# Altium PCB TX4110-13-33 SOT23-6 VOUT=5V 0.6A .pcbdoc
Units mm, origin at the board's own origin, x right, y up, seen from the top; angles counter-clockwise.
Board outline 37.13 x 43.21 mm, 2 copper layers (Top Layer, Bottom Layer); 14 components, 13 nets, 38 pads, 95 vias.
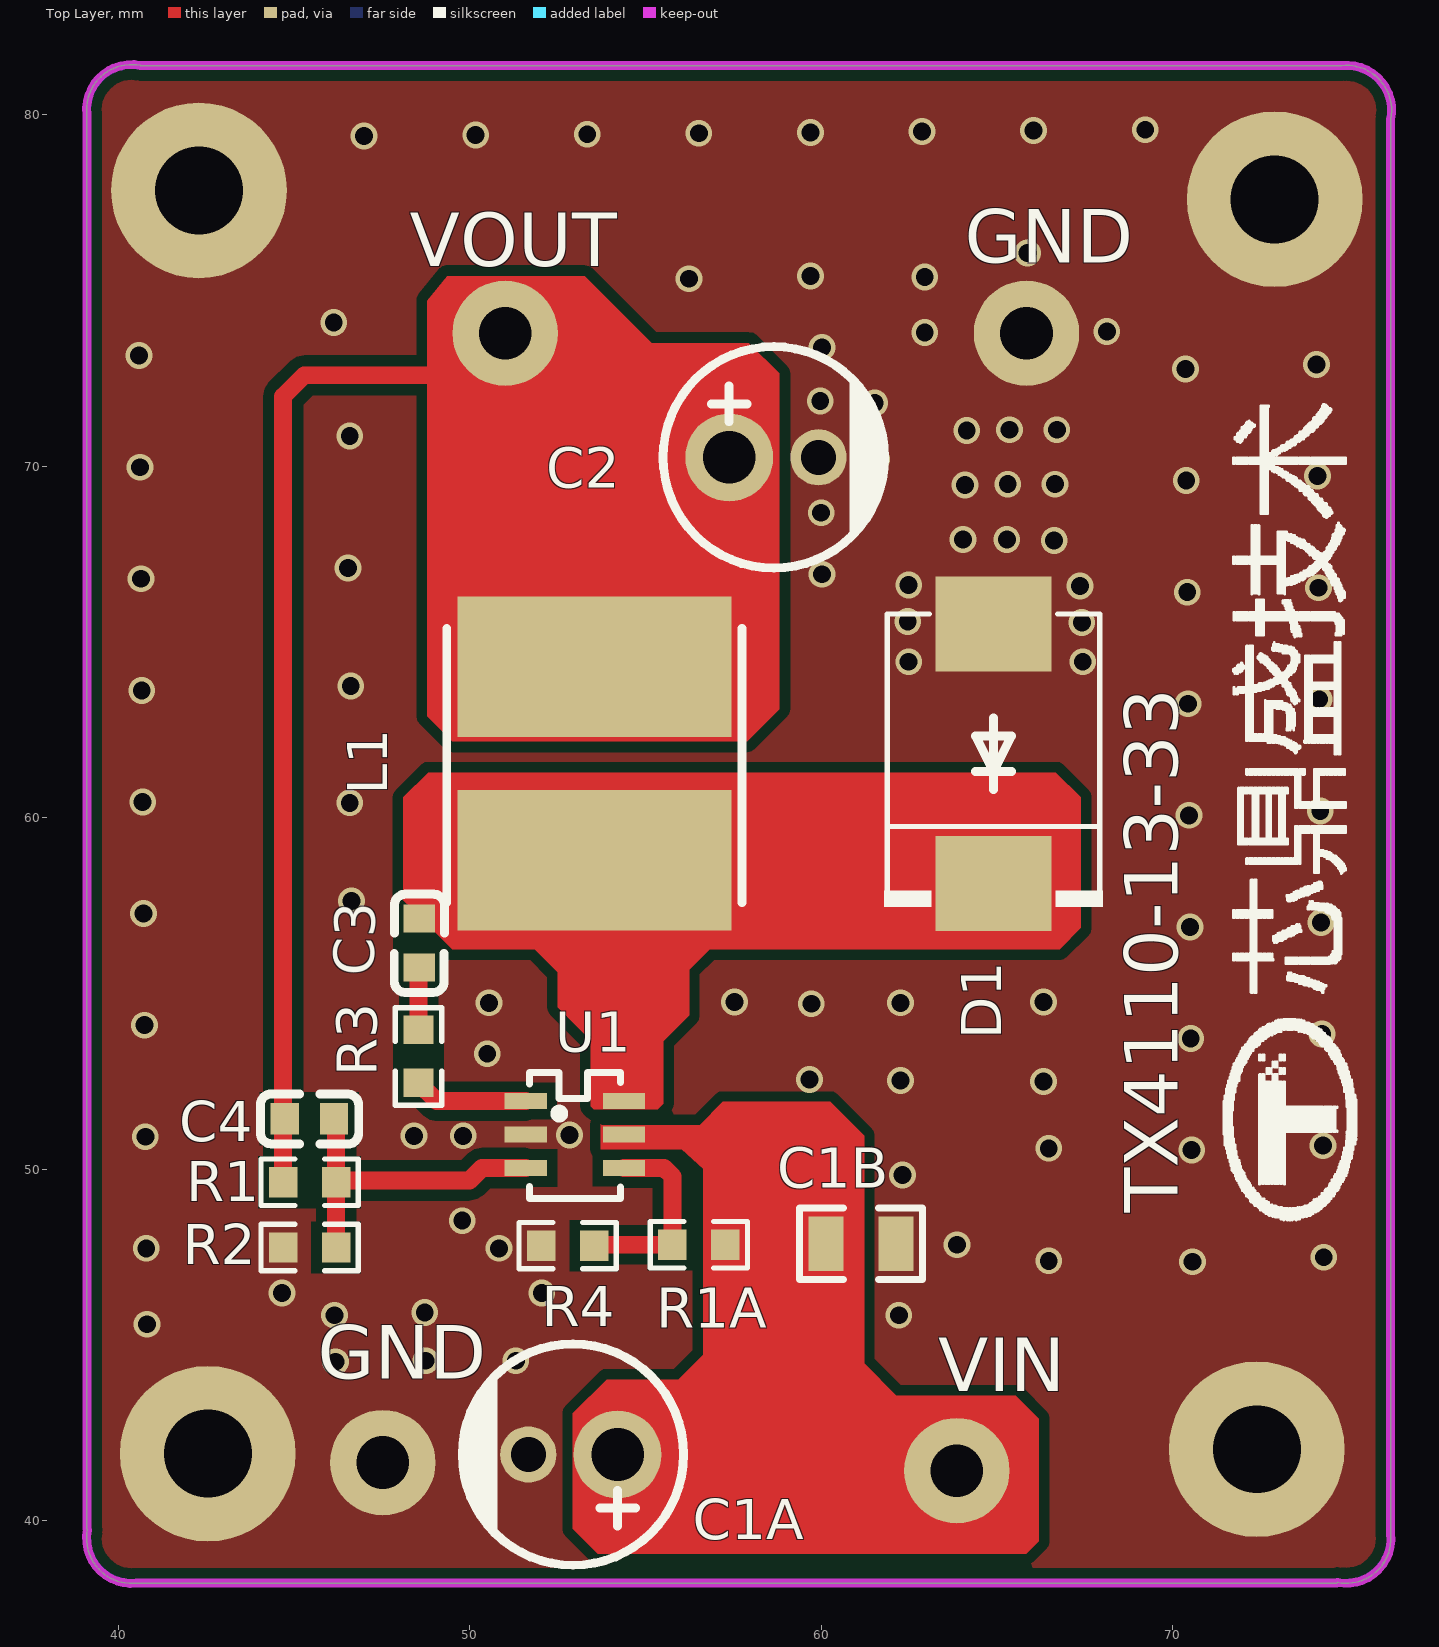
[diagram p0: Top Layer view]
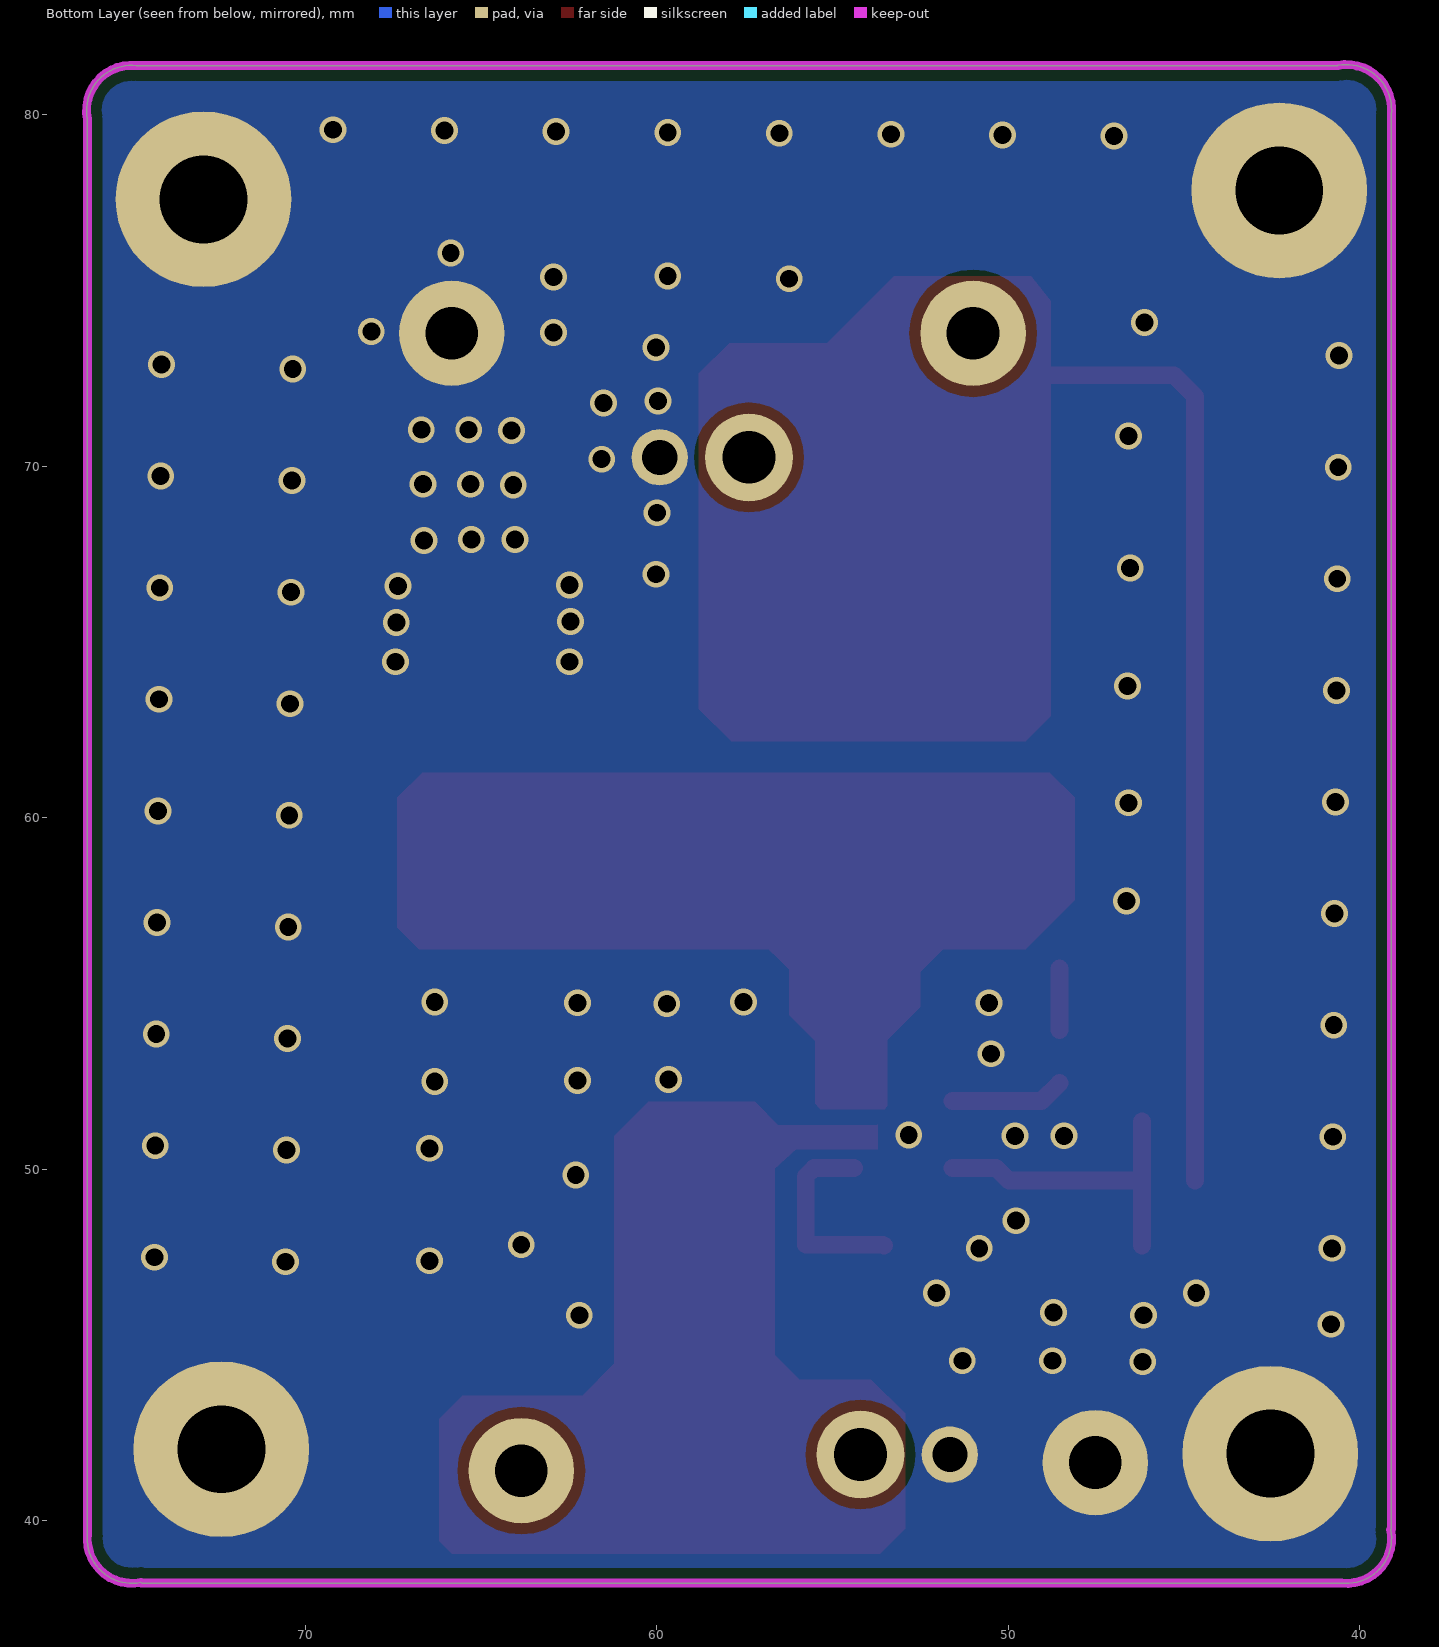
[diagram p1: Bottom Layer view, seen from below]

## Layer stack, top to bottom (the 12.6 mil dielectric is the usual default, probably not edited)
Top Layer: signal copper 0.0356
Dielectric: dielectric 0.32, FR-4, Dk 4.8
Bottom Layer: signal copper 0.0356

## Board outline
40.513,38.227 cw(c40.372,39.496) 39.121,39.746 39.104,39.763 39.104,80.015 cw(c40.372,80.155) 40.622,81.407 40.628,81.402 74.808,81.402 cw(c74.948,80.133) 76.2,79.883 76.199,79.882 76.199,39.638 cw(c74.93,39.497) 74.68,38.245 74.661,38.227

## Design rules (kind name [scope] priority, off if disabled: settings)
Clearance [All] p1: gap=0.305
PlaneConnect [All] p1: planeconnectstyle=Direct reliefexpansion=0.508 reliefentries=4 reliefconductorwidth=0.254 reliefairgap=0.254
PolygonConnect [All] p1: connectstyle=Direct reliefconductorwidth=0.254 reliefentries=4 polygonreliefangle="90 Angle"
RoutingVias [All] p1: holewidth=0.711 width=1.27 viastyle="Through Hole" minholewidth=0.711 minwidth=1.27 maxholewidth=0.711 maxwidth=1.27
SilkscreenOverComponentPads [All] p1: minsilkscreentomaskgap=0.254
SolderMaskExpansion [All] p1: expansion=0.102
TestPointUsage [All] p1: valid=0 allowmultiple=FALSE
Testpoint [All] p1: side=3 testpointundercomponent=TRUE minsize=1.016 maxsize=2.54 preferedsize=1.524 minholesize=0 maxholesize=1.016 preferedholesize=0.813 testpointgrid=0.025 style=297 order=0-112345678
Width [All] p1: maxlimit=2.54 minlimit=0.508 preferedwidth=0.508
22 further rules are at their usual default settings.

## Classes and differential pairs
net class NewClass: VIN

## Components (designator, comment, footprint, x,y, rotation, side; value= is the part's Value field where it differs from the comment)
C1A "100UF" CAP-TH_BD6.3-P2.50-D1.0-FD 52.934,41.885 r180 top (schematic designator C1)
C1B "0.1u" 0805 62.128,47.879 r180 top (schematic designator C6)
C2 "470uF" CAP-TH_BD6.3-P2.50-D1.0-FD 58.649,70.256 r0 top
C3 "0.1u" C0603 48.565,56.439 r90 top (schematic designator C4)
C4 "NC" C0603 45.433,51.435 r180 top (schematic designator C6)
D1 "SS510SMC" SMC_L6.9-W5.9-LS7.9-RD 64.897,61.824 r90 top (schematic designator D2)
L1 "10uH" IND-SMD_L7.8-W7.0_GCD75 53.543,61.544 r90 top (schematic designator L2)
R1 "300K 1%" R0603 45.441,49.632 r180 top (schematic designator R4)
R1A "1k" R0603 56.515,47.854 r180 top (schematic designator R3)
R2 "51k 1%" R0603 45.441,47.777 r0 top (schematic designator R5)
R3 "5.1k" R0603 48.539,53.213 r270 top (schematic designator R2)
R4 "NC" R0603 52.781,47.828 r0 top (schematic designator R3)
TX4110-13-33 "Comment" LOGO 72.822,51.435 r90 top
U1 "TX4137" SOT-23-6 51.587,51.943 r0 top

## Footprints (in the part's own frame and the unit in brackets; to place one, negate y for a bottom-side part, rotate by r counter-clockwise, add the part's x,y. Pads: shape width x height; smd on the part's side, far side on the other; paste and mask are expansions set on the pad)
0805 [mm]
  rect 1x1.55 smd: 1(0,0) 2(2,0)
  silkscreen extent -0.75,-1.02 2.75,1.02
C0603 [mm]
  rect 0.8x0.9 smd: 1(-0.7,0) 2(0.7,0)
  silkscreen extent -1.41,-0.71 1.39,0.72
CAP-TH_BD6.3-P2.50-D1.0-FD [mm]
  round 2.5 hole 1.5: 1(-1.27,0)
  round 1.6 hole 1: 2(1.27,0)
  silkscreen extent -3.15,-3.15 3.17,3.15
IND-SMD_L7.8-W7.0_GCD75 [mm]
  rect 4x7.8 smd: 1(-2.75,0) 2(2.75,0)
  silkscreen extent -3.95,-4.2 3.85,4.2
LOGO [mm]
  silkscreen extent -2.88,-2.39 20.34,1.37
R0603 [mm]
  rect 0.806x0.864 smd: 1(-0.753,0) 2(0.753,0)
  silkscreen extent -1.39,-0.66 1.39,0.66
SMC_L6.9-W5.9-LS7.9-RD [mm]
  rect 2.7x3.3 smd: 1(-3.686,0) 2(3.686,0)
  silkscreen extent -4.36,-3.1 3.98,3.1
SOT-23-6 [mm]
  rect 1.2x0.467 smd: 1(0,0) 2(0,-0.952) 3(0,-1.905) 4(2.794,-1.905) 5(2.794,-0.952) 6(2.794,0)
  silkscreen extent 0.11,-2.77 2.7,0.81

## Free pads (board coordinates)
  round 5 hole 2.5: 2(42.291,77.851) 2(42.545,41.91) 2(72.39,42.037) 2(72.898,77.597)
  round 3 hole 1.5: 4(47.523,41.656) 5(65.837,73.787) 9(63.856,41.427) 10(51.003,73.787)

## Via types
v1: diameter 0.762, hole 0.508, Top Layer to Bottom Layer, tented both sides, 95 vias

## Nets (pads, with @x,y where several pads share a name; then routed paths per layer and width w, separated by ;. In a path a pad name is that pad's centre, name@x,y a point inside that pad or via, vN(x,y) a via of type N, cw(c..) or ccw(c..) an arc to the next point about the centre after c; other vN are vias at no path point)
BS: R3.2 U1.1 | length 3.3
  Top Layer w0.508: R3.2 49.056,51.943 U1.1
EN: R1A.2 R4.2 U1.4 | length 5.7
  Top Layer w0.508: R4.2 53.56,47.854 R1A.2 55.762,49.801 55.524,50.038 U1.4
FB: C4.1 R1.1 R2.2 U1.3 | length 9.1
  Top Layer w0.508: R2.2@46.194,47.828 R1.1@46.194,49.682 ; C4.1@46.194,51.356 R1.1@46.194,49.682 ; U1.3 50.343,50.038 49.987,49.682 R1.1@46.194,49.682
GND: C1A.2 C1B.1 C2.2 D1.2 pad.2 pad.4 pad.5 R2.1 R4.1 U1.2
  other v1: 46.177,44.526 48.743,44.552 51.308,44.552 40.818,45.593 46.152,45.847 62.205,45.847 48.717,45.923 44.653,46.482 52.045,46.482 70.561,47.371 66.472,47.396 74.295,47.498 40.792,47.752 50.825,47.752 63.856,47.854 49.784,48.539 62.306,49.835 70.536,50.546 66.472,50.597 74.27,50.673 40.767,50.927 48.412,50.952 49.809,50.952 52.832,50.978 66.319,52.502 62.255,52.527 59.665,52.553 50.495,53.289 70.51,53.721 74.244,53.848 40.742,54.102 59.715,54.712 50.546,54.737 62.255,54.737 57.531,54.762 66.319,54.762 70.485,56.896 74.219,57.023 40.716,57.277 46.634,57.633 70.46,60.071 74.193,60.198 46.584,60.427 40.691,60.452 70.434,63.246 74.168,63.373 40.665,63.627 46.609,63.754 62.484,64.44 67.437,64.44 67.412,65.557 62.459,65.583 70.409,66.421 74.143,66.548 67.361,66.599 62.484,66.624 40.64,66.802 60.02,66.929 46.533,67.107 66.624,67.894 64.033,67.92 65.278,67.92 59.995,68.682 64.084,69.469 65.303,69.494 66.65,69.494 70.383,69.596 74.117,69.723 40.615,69.977 61.57,70.206 46.584,70.866 64.135,71.018 65.354,71.044 66.7,71.044 61.519,71.806 59.969,71.857 70.358,72.771 74.092,72.898 40.589,73.152 60.02,73.381 62.941,73.812 68.123,73.838 46.126,74.092 56.236,75.336 62.941,75.387 59.69,75.413 65.862,76.073 46.99,79.4 50.165,79.426 53.34,79.451 56.515,79.477 59.69,79.502 62.865,79.527 66.04,79.553 69.215,79.578
IMLM: 
R2_1: C3.1 R3.1 | length 1.7
  Top Layer w0.508: R3.1 C3.1@48.539,55.713
S$490: 
SW: C3.2 D1.1 L1.1 U1.6 | length 6.3
  Top Layer w0.508: L1.1@53.95,58.388 53.95,53.442 54.254,53.137 55.22,53.137
U3_6: 
U3_7: 
VIN: C1A.1 C1B.2 pad.9 R1A.1 U1.5 | length 27.2
  Top Layer w0.508: C1A.1@53.95,42.364 54.204,42.11 C1A.1 ; C1A.1@54.316,41.997 60.198,41.997 63.286,41.997 pad.9 ; U1.5 59.372,50.991 60.128,50.235 C1B.2 ; R1A.1 57.294,47.879 C1B.2 ; 60.128,42.309 C1B.2
VIN1: 
VOUT: C2.1 C4.2 L1.2 pad.10 R1.2 | length 40.9
  Top Layer w0.508: R1.2@44.687,49.682 44.687,71.992 45.288,72.593 49.809,72.593 ; pad.10 52.934,71.857 52.934,64.903 L1.2 L1.2@55.074,62.763 ; C2.1@57.379,69.748 C2.1

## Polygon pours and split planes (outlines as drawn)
GND on Top Layer "Top Layer-No Net" (solid, remove dead copper, pour order 2): 39.497,81.153 76.2,81.153 76.2,38.227 39.243,38.227 39.116,38.1 39.116,81.153
GND on Bottom Layer "Top Layer-GND" (solid, remove dead copper, pour order 6): 38.938,81.026 75.895,81.026 76.022,80.899 76.022,37.973 38.938,37.973 38.811,37.846 38.938,37.973 38.938,81.026

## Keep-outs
Keep-Out Layer:
  lines w0.254: 39.104,39.763 39.104,80.015 cw(c40.372,80.155) 40.622,81.407 ; 39.121,39.746 ccw(c40.372,39.496) 40.513,38.227 74.661,38.227 ; 40.628,81.402 74.808,81.402 cw(c74.948,80.133) 76.2,79.883 ; 74.68,38.245 ccw(c74.93,39.497) 76.199,39.638 76.199,79.882

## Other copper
Top Layer:
  region net VIN: 53.721,51.283 53.746,51.257 56.54,51.257 57.201,51.918 60.249,51.918 61.214,50.952 61.214,44.475 62.128,43.561 65.532,43.561 66.192,42.901 66.192,39.421 65.837,39.065 53.645,39.065 52.934,39.776 52.934,43.053 53.899,44.018 55.931,44.018 56.642,44.729 56.642,50.011 56.035,50.571 53.721,50.571
  region net SW: 53.518,51.714 55.347,51.714 55.499,51.867 55.499,53.645 56.236,54.381 56.236,55.677 57.125,56.566 57.125,57.633 52.302,57.633 51.791,57.048 51.791,56.312 52.502,55.601 52.502,54.61 53.442,53.67 53.442,51.791
  region net SW: 48.108,60.579 48.819,61.29 66.675,61.29 67.386,60.579 67.386,56.871 66.777,56.261 49.505,56.261 48.108,57.658
  region net VOUT: 49.352,75.413 53.264,75.413 55.169,73.508 57.937,73.508 58.801,72.644 58.801,63.094 57.887,62.179 49.505,62.179 48.793,62.89 48.793,74.714

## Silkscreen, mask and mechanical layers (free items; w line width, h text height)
Top Overlay:
  text "GND" at 64.084,75.794 h1.52
  text "VOUT" at 48.285,75.692 h1.52
  text "GND" at 45.669,44.044 h1.52
  text "VIN" at 63.322,43.688 h1.52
